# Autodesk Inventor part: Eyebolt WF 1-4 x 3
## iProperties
Company: Mountain Blue Industries Ltd.
Category: Fasteners
Shininess: 64.0
Length Units: 11272
Angle Units: 11279
Time Units: 11290
Mass Units: 11286
Length Display Precision: 3
Angle Display Precision: 2
Compacted: True
Part Number: Eyebolt WF 1-4 x 3
Document SubType Name: Modeling
Created: 2002-11
Designer: QBZ
Material: Steel, Mild
Description: 1/4 X 3 Eyebolt
Density: 0.0
Volumn: 0.0
Area: 0.0
PropertySet Name: Model Information
Control State: 0
Master: False
Checked Out: False
Length: 1
Author: QBZ
Revision Number: A
Title: Eyebolt WireForm
Keywords: Eyebolt
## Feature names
1. Sweep1
2. Chamfer1
